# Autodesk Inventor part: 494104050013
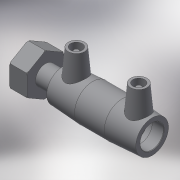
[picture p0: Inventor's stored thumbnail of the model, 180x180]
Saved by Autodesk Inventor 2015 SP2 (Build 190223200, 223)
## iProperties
Created: 2017-06
Part Number: 494104050013
Material: Generic
Description: PLASSON FEMALE FREE NUT TRANSITION COUPLER 50-1"
Document SubType Name: Modeling
Designer: KIM
Mass: 55.0731 g
Surface Area: 148.067 cm^2
Volume: 55.0731 cm^3
Density: 1 g/cm^3
Appearance: Default
Author: KIM
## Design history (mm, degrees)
derived "494104.ipt"
feature "Solid1::494104.ipt"
tag "TaggingFeature1"
body "Solid1"
other parameters: "d2" = 67, "d3" = 49, "d4" = 33.33333, "d5" = 60.3, "d6" = 47.5, "d8" = 168 deg, "d10" = 19.6, "d11" = 6.53333, "d29" = 52, "d30" = 14, "d31" = 35, "d34" = 5 deg, "d41" = 4, "d42" = 14, "d43" = 0, "d48" = 3, "d49" = 0, "d55" = 36, "d57" = 23, "d80" = 1, "d83" = 18, "d84" = 11.88, "d85" = 1.188, "d86" = 31.1616, "d87" = 38.952, "d88" = 58.428, "d89" = 67, "d90" = 1.16856, "d94" = 0, "d95" = 1.188, "d96" = 27.2664, "L_" = 136, "L_1" = 49, "D_1" = 67, "A_" = 52, "d_2" = 12, "L_2" = 36, "D_" = 23, "G_" = 38.952
